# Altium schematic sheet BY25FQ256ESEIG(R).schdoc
size 127 x 101 mm
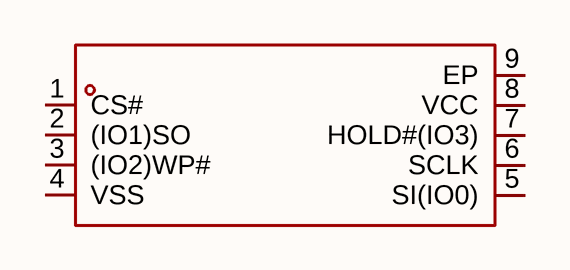
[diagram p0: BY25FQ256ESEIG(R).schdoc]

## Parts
U?  by25fq256eseig(r)  [WSON-8_L8.0-W6.0-P1.27-TL-1]  (value not drawn)

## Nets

Not connected (* = marked no-connect by the designer): U? 1(CS#) 2((IO1)SO) 3((IO2)WP#) 4(VSS) 5(SI(IO0)) 6(SCLK) 7(HOLD#(IO3)) 8(VCC) 9(EP)

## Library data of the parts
U? = by25fq256eseig(r): Manufacturer: BOYAMICRO(博雅); AddInBom: yes; ModelId: f7358afd81b248ccb497b4df88085798; ModelTransform: 315.7474,236.22,0,0,0,0,0,0,0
